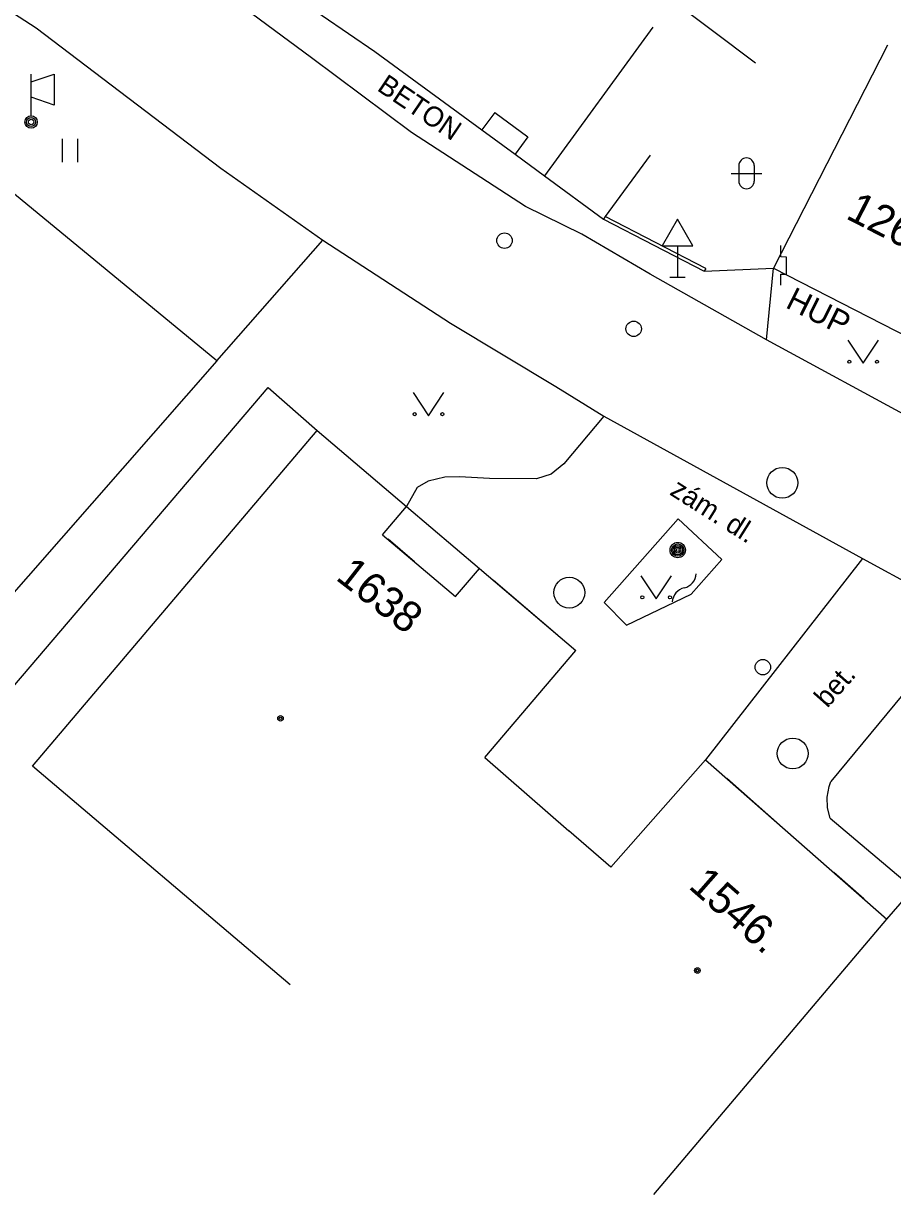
# Model space of a CAD drawing. Extents: x -539244 to -537359, y -1183785 to -1181851.
# Drawn here: x -538505.93 to -538477.73, y -1183472.91 to -1183434.91 of the extents above; entities that cross this region are included whole.
import ezdxf

# ---------------------------------------------------------------- set-up
doc = ezdxf.new("R2010")
doc.units = 0
for name, color, linetype in [('Vrstva 10', 7, 'Continuous'), ('Vrstva 11', 7, 'Continuous'), ('Vrstva 23', 7, 'Continuous'), ('Vrstva 24', 7, 'Continuous'), ('Vrstva 25', 7, 'Continuous'), ('Vrstva 27', 7, 'Continuous'), ('Vrstva 28', 7, 'Continuous'), ('Vrstva 33', 7, 'Continuous'), ('Vrstva 34', 7, 'Continuous'), ('Vrstva 36', 7, 'Continuous'), ('Vrstva 39', 7, 'Continuous'), ('Vrstva 40', 7, 'Continuous'), ('Vrstva 41', 7, 'Continuous'), ('Vrstva 47', 7, 'Continuous'), ('Vrstva 5', 7, 'Continuous'), ('Vrstva 6', 7, 'Continuous'), ('Vrstva 7', 7, 'Continuous'), ('Vrstva 8', 7, 'Continuous')]:
    doc.layers.add(name, color=color, linetype=linetype)

msp = doc.modelspace()

# ---------------------------------------------------------------- linework, layer by layer
at = {"layer": 'Vrstva 10'}
for p, q in [((-538516.91, -1183427.65), (-538505.52, -1183435.06)), ((-538496.58, -1183436.03), (-538502.21, -1183431.87)), ((-538505.52, -1183435.06), (-538499.52, -1183439.61)), ((-538490.639, -1183437.804), (-538491.053, -1183438.369)), ((-538490.639, -1183437.804), (-538489.563, -1183438.593)), ((-538489.563, -1183438.593), (-538489.977, -1183439.158)), ((-538499.52, -1183439.61), (-538496.22, -1183441.95)), ((-538474.11, -1183449.36), (-538481.82, -1183445.18)), ((-538488.66, -1183446.69), (-538487.1, -1183447.65)), ((-538487.1, -1183447.65), (-538478.71, -1183452.27)), ((-538494.277, -1183451.501), (-538493.5, -1183450.588)), ((-538494.277, -1183451.501), (-538491.915, -1183453.511)), ((-538478.71, -1183452.27), (-538475.3, -1183454.13)), ((-538491.915, -1183453.511), (-538491.138, -1183452.598))]:
    msp.add_line(p, q, dxfattribs=at)
for points in [[(-538489.64, -1183440.85), (-538493.34, -1183438.45), (-538496.58, -1183436.03)], [(-538481.82, -1183445.18), (-538485.6, -1183443.05), (-538487.81, -1183441.75), (-538489.64, -1183440.85)], [(-538496.22, -1183441.95), (-538492.07, -1183444.64), (-538488.66, -1183446.69)]]:
    msp.add_lwpolyline(points, dxfattribs=at)
at = {"layer": 'Vrstva 11'}
for p, q in [((-538481.82, -1183445.18), (-538481.59, -1183442.85)), ((-538483.27, -1183452.3), (-538484.69, -1183450.99)), ((-538478.71, -1183452.27), (-538483.8, -1183458.8)), ((-538475.3, -1183454.13), (-538479.73, -1183459.51)), ((-538479.75, -1183460.7), (-538477.05, -1183462.98))]:
    msp.add_line(p, q, dxfattribs=at)
for points in [[(-538487.1, -1183447.65), (-538488.4, -1183449.2), (-538488.81, -1183449.54), (-538489.28, -1183449.69), (-538490.81, -1183449.68), (-538491.78, -1183449.62), (-538492.26, -1183449.63), (-538492.8, -1183449.76), (-538493.16, -1183449.97), (-538493.5, -1183450.588)], [(-538484.69, -1183450.99), (-538487.09, -1183453.7), (-538486.36, -1183454.44), (-538484.27, -1183453.43), (-538483.27, -1183452.3)], [(-538479.75, -1183460.7), (-538479.843, -1183460.365), (-538479.857, -1183460.017), (-538479.792, -1183459.675), (-538479.73, -1183459.51)]]:
    msp.add_lwpolyline(points, dxfattribs=at)
at = {"layer": 'Vrstva 23'}
for q in [(-538521.68, -1183427.73), (-538496.22, -1183441.95), (-538514.69, -1183462.99)]:
    msp.add_line((-538499.65, -1183445.86), q, dxfattribs=at)
at = {"layer": 'Vrstva 24'}
for p, q in [((-538481.36, -1183442.489), (-538481.36, -1183442.121)), ((-538481.177, -1183442.491), (-538481.36, -1183442.489)), ((-538481.177, -1183443.043), (-538481.177, -1183442.491)), ((-538481.36, -1183443.41), (-538481.36, -1183443.043)), ((-538481.36, -1183443.043), (-538481.177, -1183443.043))]:
    msp.add_line(p, q, dxfattribs=at)
for centre, start, end in [((-538484.598, -1183452.738), 282.7318, 356.4716), ((-538484.378, -1183453.714), 102.7318, 176.4715)]:
    msp.add_arc(centre, 0.5, start, end, dxfattribs=at)
at = {"layer": 'Vrstva 25'}
for radius in [0.25, 0.2, 0.15, 0.1, 0.05]:
    msp.add_circle((-538484.7, -1183452), radius, dxfattribs=at)
at = {"layer": 'Vrstva 27'}
for centre in [(-538481.308, -1183449.818), (-538488.22, -1183453.38), (-538480.97, -1183458.6)]:
    msp.add_circle(centre, 0.5, dxfattribs=at)
at = {"layer": 'Vrstva 28'}
for centre in [(-538490.32, -1183441.96), (-538486.13, -1183444.82), (-538481.94, -1183455.8)]:
    msp.add_circle(centre, 0.25, dxfattribs=at)
at = {"layer": 'Vrstva 33'}
msp.add_line((-538505.68, -1183437.91), (-538505.68, -1183436.56), dxfattribs=at)
msp.add_lwpolyline([(-538505.68, -1183436.81), (-538504.93, -1183436.56), (-538504.93, -1183437.56), (-538505.68, -1183437.31)], dxfattribs=at)
for radius in [0.2, 0.145, 0.0876]:
    msp.add_circle((-538505.681, -1183438.111), radius, dxfattribs=at)
at = {"layer": 'Vrstva 34'}
for p, q in [((-538484.71, -1183442.134), (-538484.71, -1183443.15)), ((-538484.96, -1183443.15), (-538484.46, -1183443.15))]:
    msp.add_line(p, q, dxfattribs=at)
msp.add_lwpolyline([(-538485.21, -1183442.134), (-538484.21, -1183442.134), (-538484.71, -1183441.266)], close=True, dxfattribs=at)
at = {"layer": 'Vrstva 36'}
for p, q in [((-538504.663, -1183439.41), (-538504.663, -1183438.66)), ((-538504.162, -1183439.41), (-538504.162, -1183438.66)), ((-538482.97, -1183439.777), (-538481.97, -1183439.777)), ((-538482.721, -1183439.526), (-538482.721, -1183440.027)), ((-538482.22, -1183439.526), (-538482.22, -1183440.027))]:
    msp.add_line(p, q, dxfattribs=at)
for points in [[(-538479.186, -1183445.19), (-538478.686, -1183445.94), (-538478.186, -1183445.19)], [(-538493.286, -1183446.891), (-538492.786, -1183447.641), (-538492.286, -1183446.891)], [(-538485.902, -1183452.83), (-538485.402, -1183453.58), (-538484.902, -1183452.83)]]:
    msp.add_lwpolyline(points, dxfattribs=at)
for centre in [(-538479.136, -1183445.89), (-538478.237, -1183445.89), (-538493.236, -1183447.591), (-538492.337, -1183447.591), (-538485.852, -1183453.53), (-538484.953, -1183453.53)]:
    msp.add_circle(centre, 0.05, dxfattribs=at)
for centre, start, end in [((-538482.47, -1183439.527), 0, 180), ((-538482.47, -1183440.027), 180, 0)]:
    msp.add_arc(centre, 0.25, start, end, dxfattribs=at)
at = {"layer": 'Vrstva 39'}
for centre, radius in [((-538497.59, -1183457.459), 0.09), ((-538497.59, -1183457.459), 0.0398), ((-538484.062, -1183465.641), 0.09), ((-538484.062, -1183465.641), 0.0398)]:
    msp.add_circle(centre, radius, dxfattribs=at)
at = {"layer": 'Vrstva 5'}
for p, q in [((-538482.18, -1183436.2), (-538496.58, -1183425.34)), ((-538500.94, -1183431.43), (-538494.53, -1183435.82)), ((-538485.511, -1183435.033), (-538489.023, -1183439.857)), ((-538477.9, -1183435.62), (-538481.59, -1183442.85)), ((-538494.53, -1183435.82), (-538491.053, -1183438.369)), ((-538491.053, -1183438.369), (-538489.977, -1183439.158)), ((-538489.977, -1183439.158), (-538489.023, -1183439.857)), ((-538485.596, -1183439.19), (-538487.05, -1183441.178)), ((-538489.023, -1183439.857), (-538487.11, -1183441.26)), ((-538487.05, -1183441.178), (-538487.11, -1183441.26)), ((-538481.59, -1183442.85), (-538477.18, -1183445.11)), ((-538505.64, -1183459.01), (-538496.4, -1183448.12)), ((-538496.4, -1183448.12), (-538493.5, -1183450.588)), ((-538493.5, -1183450.588), (-538491.138, -1183452.598)), ((-538491.138, -1183452.598), (-538488.01, -1183455.26)), ((-538490.96, -1183458.73), (-538488.01, -1183455.26)), ((-538486.87, -1183462.29), (-538483.8, -1183458.8)), ((-538483.8, -1183458.8), (-538477.92, -1183463.97)), ((-538497.273, -1183466.109), (-538505.64, -1183459.01)), ((-538485.48, -1183472.91), (-538477.92, -1183463.97))]:
    msp.add_line(p, q, dxfattribs=at)
msp.add_lwpolyline([(-538477.92, -1183463.97), (-538477.05, -1183462.98), (-538476.44, -1183462.28)], dxfattribs=at)
at = {"layer": 'Vrstva 6'}
for p, q in [((-538493.24, -1183452.38), (-538494.1, -1183451.65)), ((-538488.6, -1183454.76), (-538490.68, -1183452.99)), ((-538481.3, -1183461), (-538483.11, -1183459.4)), ((-538486.87, -1183462.29), (-538488.23, -1183461.11)), ((-538478.66, -1183463.32), (-538479.64, -1183462.46))]:
    msp.add_line(p, q, dxfattribs=at)
at = {"layer": 'Vrstva 7'}
for p, q in [((-538487.11, -1183441.26), (-538483.84, -1183442.95)), ((-538483.794, -1183442.861), (-538487.05, -1183441.178)), ((-538483.794, -1183442.861), (-538483.84, -1183442.95)), ((-538507.87, -1183458.31), (-538497.99, -1183446.73)), ((-538497.99, -1183446.73), (-538496.4, -1183448.12)), ((-538490.96, -1183458.73), (-538488.23, -1183461.11))]:
    msp.add_line(p, q, dxfattribs=at)
at = {"layer": 'Vrstva 8'}
msp.add_line((-538483.84, -1183442.95), (-538481.59, -1183442.85), dxfattribs=at)

# ---------------------------------------------------------------- texts
at = {"layer": 'Vrstva 40'}
for s, rotation, p in [('BETON', 325.9442, (-538494.489, -1183437.067)), ('zám. dl.', 327.7344, (-538484.995, -1183450.182)), ('bet.', 48.3626, (-538479.847, -1183457.148))]:
    msp.add_text(s, height=0.65, rotation=rotation, dxfattribs=at).set_placement(p)
at = {"layer": 'Vrstva 41'}
msp.add_text('HUP', height=0.75, rotation=333.5373, dxfattribs=at).set_placement((-538481.238, -1183444.116))
at = {"layer": 'Vrstva 47'}
for s, rotation, p in [('126.', 332.8661, (-538479.285, -1183441.222)), ('1638', 322.0663, (-538495.833, -1183452.936)), ('1546.', 318.6764, (-538484.386, -1183462.946))]:
    msp.add_text(s, height=1, rotation=rotation, dxfattribs=at).set_placement(p)

doc.saveas('drawing.dxf')
